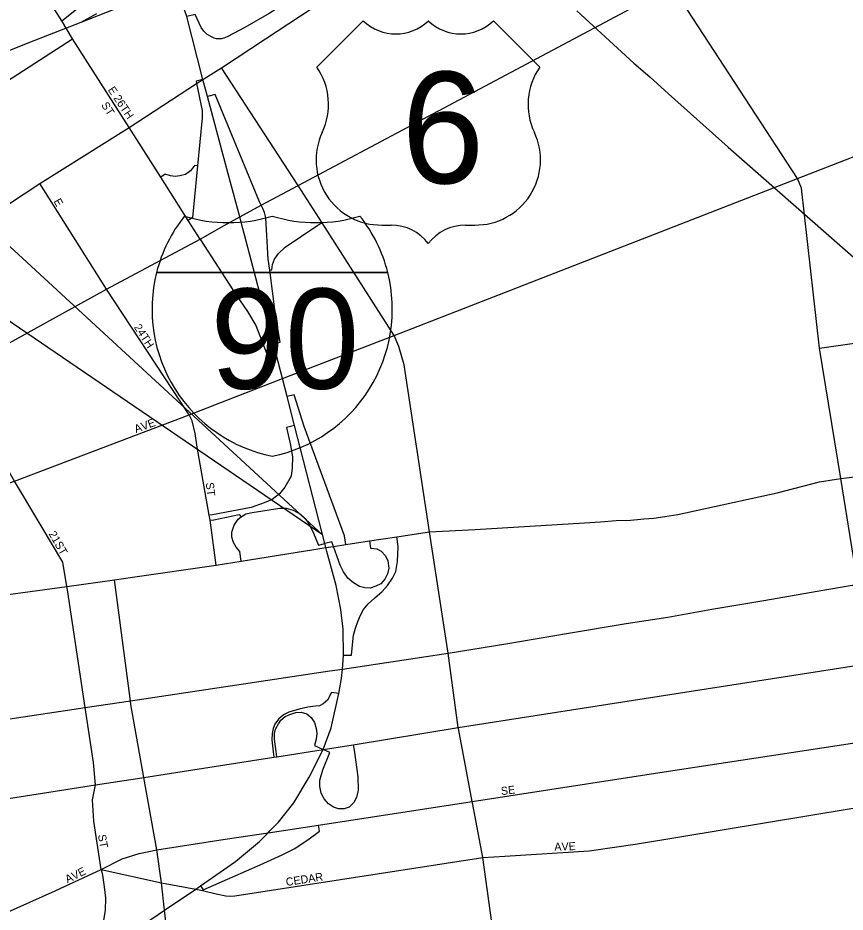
# Model space of a CAD drawing. Extents: x -561 to 1170, y 0 to 846.
# Drawn here: x 254.24 to 268.18, y 287.78 to 302.86 of the extents above; entities that cross this region are included whole.
import ezdxf

# ---------------------------------------------------------------- set-up
doc = ezdxf.new("R2010")
doc.units = 0
for name, color, linetype in [('GM_X_City_Street', 7, 'Continuous'), ('GM_X_City_Street_Text', 7, 'Continuous'), ('GM_X_Interchange_Ramps', 7, 'Continuous'), ('GM_X_Interstate_Location', 7, 'Continuous'), ('GM_X_Interstate_Route', 7, 'Continuous'), ('GM_X_Interstate_Shield', 7, 'Continuous'), ('GM_X_Rail_Line', 7, 'Continuous'), ('GM_X_US_Location', 7, 'Continuous'), ('GM_X_US_Route', 7, 'Continuous'), ('GM_X_US_Shield', 7, 'Continuous'), ('SH_Text', 7, 'Continuous')]:
    doc.layers.add(name, color=color, linetype=linetype)

msp = doc.modelspace()

# ---------------------------------------------------------------- linework, layer by layer
at = {"layer": 'GM_X_City_Street'}
for points in [[(258.41, 302.501), (259.395, 303.146), (259.615, 303.29), (263.672, 305.898), (272.749, 311.733)], [(267.887, 279.37), (268.77, 282.651), (269.722, 286.301), (268.995, 289.646), (268.821, 290.708), (268.615, 291.976), (268.397, 293.307), (268.107, 295.088), (267.748, 297.285), (267.443, 299.985), (267.379, 300.146), (265.263, 303.388), (263.672, 305.898), (262.345, 307.991), (260.676, 310.495)], [(254.977, 302.804), (255.778, 303.45), (256.632, 304.089), (258.285, 305.362), (262.345, 307.991)], [(254.977, 302.804), (254.468, 303.615), (254.278, 303.919)], [(255.157, 302.502), (254.977, 302.804)], [(246.465, 296.891), (248.882, 298.451), (249.463, 298.826), (255.157, 302.502)], [(247.385, 295.394), (247.404, 295.407), (249.829, 296.962), (250.484, 297.381), (252.174, 298.464), (254.608, 300.065), (256.113, 301.01), (257.249, 301.751), (257.352, 301.819), (257.67, 302.016), (258.41, 302.501)], [(256.644, 300.171), (256.113, 301.01), (255.157, 302.502)], [(248.99, 293.083), (249.153, 293.177), (249.468, 293.351), (249.807, 293.478), (251.624, 294.13), (252.497, 294.443), (254.178, 295.045), (257.124, 296.16), (258.698, 296.774), (260.578, 297.501), (267.379, 300.146), (272.753, 302.236)], [(261.489, 292.143), (261.175, 294.192), (260.749, 297.003), (260.658, 297.314), (260.578, 297.501), (259.364, 299.402), (258.963, 300.032), (257.67, 302.016)], [(257.124, 296.16), (255.73, 298.283), (254.608, 300.065)], [(257.107, 299.442), (256.644, 300.171)], [(257.31, 299.122), (257.107, 299.442)], [(254.279, 294.876), (254.178, 295.045), (253.135, 296.85), (252.174, 298.464)], [(267.748, 297.285), (272.809, 298.013), (272.844, 298.014), (272.881, 298.015), (272.904, 298.016)], [(257.462, 294.469), (257.462, 294.469), (257.258, 295.615), (257.225, 295.847), (257.176, 296.063), (257.124, 296.16)], [(255.072, 293.214), (255.063, 293.268), (254.993, 293.677), (254.279, 294.876)], [(257.576, 293.626), (257.477, 294.386), (257.462, 294.469)], [(256.128, 291.381), (255.866, 293.381)], [(255.369, 291.228), (255.072, 293.214)], [(261.662, 290.876), (261.659, 290.89), (261.489, 292.143)], [(256.325, 290.043), (256.361, 290.048), (258.552, 290.39), (258.603, 290.397), (259.382, 290.519), (259.889, 290.601), (261.659, 290.89), (268.615, 291.976), (268.643, 291.98), (268.898, 292.011)], [(257.733, 289.006), (258.455, 289.117), (259.304, 289.247), (261.893, 289.646), (265.128, 290.145), (268.821, 290.708), (270.311, 290.936), (271.858, 291.194), (272.97, 291.367), (282.132, 291.486), (286.539, 291.315), (292.867, 291.083), (293.161, 291.09), (296.282, 291.164), (298.051, 291.204), (300.12, 291.102), (301.717, 291.062), (301.938, 291.049), (302.191, 291.033), (302.239, 291.023)], [(256.578, 288.828), (256.361, 290.048), (256.142, 291.28), (256.133, 291.343), (256.128, 291.381)], [(255.546, 289.922), (255.509, 290.301), (255.369, 291.228)], [(261.898, 289.619), (261.893, 289.646), (261.662, 290.876)], [(257.346, 288.14), (257.579, 288.085), (257.744, 288.054), (257.819, 288.049), (257.896, 288.054), (262.072, 288.697), (262.447, 288.721), (263.866, 288.814), (264.68, 288.93), (268.995, 289.646), (272.983, 290.301), (282.156, 290.371), (286.559, 290.115), (293.192, 289.735), (300.139, 289.365), (301.221, 289.311), (301.952, 289.275), (302.439, 289.25), (302.454, 289.249), (303.048, 289.224), (303.502, 289.196), (303.742, 289.187)], [(251.594, 289.302), (251.602, 289.304), (252.393, 289.428), (253.287, 289.568), (255.546, 289.922), (256.325, 290.043)], [(255.643, 288.497), (255.516, 289.311), (255.493, 289.672), (255.546, 289.922)], [(262.355, 286.67), (262.072, 288.697), (261.898, 289.619)], [(255.033, 288.213), (255.643, 288.497), (255.995, 288.679), (256.283, 288.769), (256.578, 288.828), (257.733, 289.006)], [(256.657, 288.271), (256.657, 288.271), (256.578, 288.828)], [(255.643, 288.497), (256.657, 288.271)], [(250.253, 285.421), (252.706, 287.107), (252.985, 287.299), (253.58, 287.563), (254.866, 288.136), (255.033, 288.213)], [(255.398, 281.67), (255.521, 282.147), (255.663, 282.665), (256.336, 285.21), (256.352, 285.27), (256.362, 285.307), (256.798, 286.944), (256.78, 287.183), (256.709, 287.81), (256.657, 288.271)], [(256.657, 288.271), (256.657, 288.271), (256.933, 288.221)], [(256.933, 288.221), (257.234, 288.167), (257.235, 288.166), (257.346, 288.14)]]:
    msp.add_lwpolyline(points, dxfattribs=at)
at = {"layer": 'GM_X_Interchange_Ramps'}
for points in [[(259.355, 303.696), (259.28, 303.645), (259.277, 303.543), (259.252, 303.458), (259.215, 303.386), (259.15, 303.328), (258.76, 303.111), (258.676, 303.058), (258.473, 302.928), (258.062, 302.693), (257.776, 302.54), (257.727, 302.519), (257.668, 302.503), (257.625, 302.5), (257.583, 302.503), (257.544, 302.514), (257.511, 302.528), (257.426, 302.577), (257.368, 302.631), (257.327, 302.694), (257.226, 302.915), (257.086, 302.876)], [(257.352, 301.819), (257.241, 301.79), (257.249, 301.751), (257.342, 301.294), (257.342, 301.173), (257.263, 300.363), (257.177, 299.488), (257.107, 299.442)], [(258.338, 299.696), (258.308, 299.753), (257.564, 301.565), (257.43, 301.528)], [(257.263, 300.363), (257.215, 300.368), (257.144, 300.276), (257.059, 300.216), (256.966, 300.19), (256.889, 300.18), (256.809, 300.191), (256.721, 300.223), (256.644, 300.171)], [(258.542, 297.362), (258.657, 297.39), (258.572, 297.895), (258.481, 298.603), (258.457, 298.785), (258.416, 299.487), (258.394, 299.576), (258.368, 299.64), (258.338, 299.696)], [(258.481, 298.603), (258.519, 298.608), (258.529, 298.7), (258.561, 298.787), (258.627, 298.882), (258.742, 298.988), (259.294, 299.359), (259.364, 299.402)], [(257.31, 299.122), (257.315, 299.114), (257.923, 298.174), (258.108, 297.904), (258.246, 297.671), (258.45, 297.148), (258.59, 297.184)], [(259.766, 293.977), (259.741, 294.124), (259.06, 295.967), (258.892, 296.498), (258.776, 296.47)], [(258.9, 295.984), (258.762, 295.951), (258.831, 295.654), (258.864, 295.455), (258.861, 295.269), (258.843, 295.126), (258.738, 294.942), (258.645, 294.831), (258.523, 294.734), (258.385, 294.677), (258.169, 294.598), (257.518, 294.477), (257.462, 294.469)], [(257.477, 294.386), (257.537, 294.394), (257.969, 294.48), (257.998, 294.441)], [(258.002, 293.695), (257.976, 293.856), (257.918, 293.934), (257.872, 294.012), (257.844, 294.099), (257.844, 294.184), (257.881, 294.305), (257.949, 294.405), (257.998, 294.441), (258.08, 294.491), (258.183, 294.517), (258.651, 294.59), (258.761, 294.59), (258.877, 294.556), (259.003, 294.487), (259.081, 294.414), (259.139, 294.323), (259.201, 294.209), (259.301, 293.964), (259.409, 293.991)], [(260.163, 294.038), (260.182, 293.913), (260.286, 293.903), (260.359, 293.866), (260.434, 293.786), (260.474, 293.699), (260.491, 293.575), (260.469, 293.483), (260.422, 293.391), (260.354, 293.316), (260.271, 293.273), (260.176, 293.242), (260.087, 293.244), (259.994, 293.267), (259.893, 293.33), (259.799, 293.408), (259.724, 293.513), (259.667, 293.629), (259.558, 293.945), (259.531, 294.022), (259.409, 293.991)], [(259.724, 292.109), (259.861, 292.113), (259.874, 292.282), (259.896, 292.447), (259.926, 292.566), (259.965, 292.68), (260.012, 292.784), (260.061, 292.881), (260.139, 292.975), (260.248, 293.071), (260.378, 293.182), (260.465, 293.284), (260.553, 293.409), (260.605, 293.523), (260.635, 293.691), (260.648, 293.945), (260.622, 294.108)], [(259.648, 291.462), (259.525, 291.48), (259.456, 291.352), (259.385, 291.289), (259.321, 291.256), (259.254, 291.252), (259.126, 291.235), (258.977, 291.202), (258.803, 291.152), (258.711, 291.105), (258.627, 291.032), (258.567, 290.946), (258.539, 290.872), (258.521, 290.789), (258.515, 290.682), (258.538, 290.478), (258.552, 290.39)], [(258.603, 290.397), (258.589, 290.488), (258.561, 290.696), (258.564, 290.788), (258.58, 290.862), (258.627, 290.954), (258.666, 291.016), (258.744, 291.076), (258.821, 291.11), (258.919, 291.142), (259.01, 291.151), (259.106, 291.12), (259.18, 291.061), (259.234, 290.974), (259.266, 290.876), (259.275, 290.79), (259.266, 290.696), (259.236, 290.586), (259.382, 290.519)], [(259.889, 290.601), (259.904, 290.508), (259.968, 290.061), (259.974, 289.834), (259.946, 289.711), (259.897, 289.624), (259.822, 289.55), (259.737, 289.52), (259.641, 289.517), (259.557, 289.547), (259.473, 289.602), (259.397, 289.688), (259.347, 289.786), (259.326, 289.896), (259.324, 290.004), (259.377, 290.175), (259.494, 290.467), (259.382, 290.519)], [(257.315, 288.222), (257.359, 288.156), (257.857, 288.371), (258.32, 288.573), (258.69, 288.745), (258.905, 288.851), (259.149, 289.016), (259.32, 289.145), (259.304, 289.247)], [(255.643, 288.497), (255.662, 288.404), (255.692, 288.207), (255.713, 288.014), (255.709, 287.809), (255.68, 287.639), (255.623, 287.466), (255.57, 287.33), (255.48, 287.221), (255.354, 287.114), (255.22, 287.002), (255.313, 286.869)]]:
    msp.add_lwpolyline(points, dxfattribs=at)
at = {"layer": 'GM_X_Interstate_Route'}
for points in [[(257.804, 300.14), (257.43, 301.528), (257.352, 301.819), (257.086, 302.876), (256.72, 303.913), (256.632, 304.089), (256.502, 304.348), (256.422, 304.515), (255.994, 305.221), (255.722, 305.615), (255.692, 305.657), (255.563, 305.845)], [(258.027, 299.307), (257.975, 299.501), (257.804, 300.14)], [(259.444, 293.859), (259.426, 293.925), (259.409, 293.991), (258.9, 295.984), (258.776, 296.47), (258.698, 296.774), (258.59, 297.184), (258.542, 297.362), (258.027, 299.307)], [(259.712, 291.947), (259.724, 292.109), (259.718, 292.551), (259.681, 292.878), (259.601, 293.287), (259.444, 293.859)], [(258.49, 289.153), (258.63, 289.297), (258.889, 289.623), (259.148, 290.054), (259.382, 290.519), (259.517, 290.886), (259.648, 291.462), (259.694, 291.717), (259.707, 291.877), (259.712, 291.947)], [(256.14, 287.423), (256.709, 287.81), (257.234, 288.167), (257.315, 288.222), (257.904, 288.633), (258.311, 288.968), (258.455, 289.117), (258.49, 289.153)]]:
    msp.add_lwpolyline(points, dxfattribs=at)
at = {"layer": 'GM_X_Interstate_Shield'}
for p, q in [((256.575, 298.564), (260.471, 298.564)), ((260.471, 298.564), (256.575, 298.564)), ((260.471, 298.564), (256.575, 298.564))]:
    msp.add_line(p, q, dxfattribs=at)
for centre, start, end in [((259.029, 297.944), 141.669, 165.8066), ((257.783, 301.934), 253.0091, 286.9909), ((259.263, 301.934), 253.0091, 286.9909), ((258.017, 297.944), 14.1934, 38.331), ((259.029, 297.944), 165.8066, 258.463), ((258.017, 297.944), 281.537, 14.1934)]:
    msp.add_arc(centre, 2.531, start, end, dxfattribs=at)
at = {"layer": 'GM_X_Rail_Line'}
for points in [[(255.302, 302.782), (255.85, 302.998)], [(255.302, 302.782), (255.566, 302.927)], [(263.658, 302.972), (264.618, 302.09), (264.888, 301.86), (265.204, 301.576), (266.211, 300.678), (268.961, 298.26)], [(234.654, 291.408), (237.388, 292.751), (238.047, 293.123), (238.727, 293.517), (242.724, 296.018), (245.044, 297.473), (248.149, 299.658), (248.75, 300.059), (249.128, 300.27), (249.659, 300.53), (250.018, 300.685), (250.312, 300.799), (250.655, 300.939), (254.511, 302.474), (255.302, 302.782)]]:
    msp.add_lwpolyline(points, dxfattribs=at)
at = {"layer": 'GM_X_US_Route'}
for points in [[(257.716, 299.354), (257.975, 299.501), (258.338, 299.696), (258.963, 300.032), (265.263, 303.388), (269.052, 305.416), (269.654, 305.741), (270.327, 306.105), (271.026, 306.485), (272.583, 307.361), (272.819, 307.435)], [(248.565, 293.674), (250.879, 295.311), (251.637, 295.819), (253.135, 296.85), (255.73, 298.283), (257.31, 299.122), (257.716, 299.354)], [(264.738, 294.404), (264.79, 294.409), (264.958, 294.422), (265.144, 294.448), (265.36, 294.483), (267.037, 294.85), (267.75, 295.033), (268.107, 295.088), (268.203, 295.103), (268.759, 295.175), (269.122, 295.23), (269.224, 295.245)], [(260.163, 294.038), (260.622, 294.108), (261.175, 294.192), (261.942, 294.232), (263.787, 294.34), (264.055, 294.357), (264.323, 294.379), (264.561, 294.388), (264.738, 294.404)], [(259.223, 293.892), (259.426, 293.925), (259.558, 293.945), (259.766, 293.977), (260.163, 294.038)], [(256.167, 293.424), (257.576, 293.626), (258.002, 293.695), (259.223, 293.892)], [(250.798, 292.674), (251.86, 292.827), (252.746, 292.954), (255.063, 293.268), (255.866, 293.381), (256.167, 293.424)], [(259.496, 291.845), (259.707, 291.877), (261.489, 292.143), (262.46, 292.302), (263.517, 292.483), (264.488, 292.642), (265.19, 292.753), (265.934, 292.887), (266.813, 293.034), (267.709, 293.191), (268.302, 293.291), (268.316, 293.293), (268.318, 293.294)], [(255.369, 291.228), (256.133, 291.343), (259.496, 291.845)], [(251.058, 290.526), (252.187, 290.739), (253.09, 290.887), (255.369, 291.228)]]:
    msp.add_lwpolyline(points, dxfattribs=at)
at = {"layer": 'GM_X_US_Shield'}
for p, q in [((260.059, 302.808), (259.275, 302.025)), ((263.034, 302.025), (262.251, 302.808)), ((260.372, 299.362), (260.528, 299.362)), ((261.781, 299.362), (261.938, 299.362))]:
    msp.add_line(p, q, dxfattribs=at)
for centre, radius, start, end in [((260.607, 303.367), 0.783, 225.573, 314.427), ((261.703, 303.367), 0.783, 225.573, 314.427), ((258.377, 301.396), 1.096, 334.5471, 35.0009), ((263.932, 301.396), 1.096, 144.9991, 205.4529), ((260.36, 300.458), 1.096, 154.8319, 270.6383), ((261.95, 300.458), 1.096, 269.3617, 25.1681), ((260.528, 298.579), 0.783, 36.8699, 90), ((261.781, 298.579), 0.783, 90, 143.1301)]:
    msp.add_arc(centre, radius, start, end, dxfattribs=at)
at = {"layer": 'SH_Text'}
msp.add_lwpolyline([(170.58, 376.04), (259.372, 294.138), (170.58, 354.718)], close=True, dxfattribs=at)

# ---------------------------------------------------------------- texts
at = {"layer": 'GM_X_City_Street_Text'}
for s, rotation, p in [('E 26TH', 303.6929, (255.747, 301.643)), ('ST', 302.7321, (255.635, 301.386)), ('E', 299.755, (254.833, 299.764)), ('24TH', 303.3094, (256.187, 297.639)), ('AVE', 20.3197, (256.228, 295.855)), ('ST', 277.12, (257.402, 295.015)), ('21ST', 299.7456, (254.75, 294.157)), ('SE', 7.1217, (262.387, 289.75)), ('ST', 280.6254, (255.584, 289.076)), ('AVE', 1.9739, (263.281, 288.812)), ('AVE', 26.565, (255.073, 288.263)), ('CEDAR', 8.6522, (258.763, 288.218))]:
    msp.add_text(s, height=0.135, rotation=rotation, dxfattribs=at).set_placement(p)
at = {"layer": 'GM_X_Interstate_Location'}
for s in ['.', '-', ',']:
    msp.add_text(s, height=0.0027, dxfattribs=at).set_placement((258.523, 297.487))
msp.add_text('90', height=0.0027, rotation=0, dxfattribs=at).set_placement((257.971, 296.928))
at = {"layer": 'GM_X_Interstate_Shield'}
msp.add_text('90', height=1.6875, dxfattribs=at).set_placement((257.483, 296.603))
at = {"layer": 'GM_X_US_Location'}
for s in ['0', '/']:
    msp.add_text(s, height=0.0027, dxfattribs=at).set_placement((261.154, 300.992))
msp.add_text('6', height=0.0027, rotation=0, dxfattribs=at).set_placement((260.882, 300.433))
at = {"layer": 'GM_X_US_Shield'}
msp.add_text('6', height=1.879, dxfattribs=at).set_placement((260.701, 300.067))

doc.saveas('drawing.dxf')
